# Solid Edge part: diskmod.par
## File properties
Author: Deepak Maini
Template: NORMENG.PAR
Last saved by: CADCIM
Revision: 6
Application: Solid Edge
Accuracy: 0.99
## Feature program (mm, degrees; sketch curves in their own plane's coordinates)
sketch for "unnamed Protrusion 1" plane through (0, 0, 0) normal (0, 0, 1) x-axis (1, 0, 0)
  line (-25.2008, 3.175) -> (-20.6375, 3.175)
  arc centre (-20.6375, 0) radius 3.175 from (-20.6375, 3.175) to (-20.6375, -3.175) cw
  line (-25.2008, -3.175) -> (-20.6375, -3.175)
  arc centre (0, 0) radius 25.4 from (-3.175, -25.2008) to (-25.2008, -3.175) cw
  line (-3.175, -25.2008) -> (-3.175, -20.6375)
  arc centre (0, -20.6375) radius 3.175 from (-3.175, -20.6375) to (3.175, -20.6375) cw
  line (3.175, -25.2008) -> (3.175, -20.6375)
  arc centre (0, 0) radius 25.4 from (25.2008, -3.175) to (3.175, -25.2008) cw
  line (25.2008, -3.175) -> (20.6375, -3.175)
  arc centre (20.6375, 0) radius 3.175 from (20.6375, -3.175) to (20.6375, 3.175) cw
  line (25.2008, 3.175) -> (20.6375, 3.175)
  arc centre (0, 0) radius 25.4 from (3.175, 25.2008) to (25.2008, 3.175) cw
  line (3.175, 25.2008) -> (3.175, 20.6375)
  arc centre (0, 20.6375) radius 3.175 from (3.175, 20.6375) to (-3.175, 20.6375) cw
  line (-3.175, 25.2008) -> (-3.175, 20.6375)
  arc centre (0, 0) radius 25.4 from (-25.2008, 3.175) to (-3.175, 25.2008) cw
extrude "unnamed Protrusion 1" add finite 3.175 along +normal
sketch for "Hole_1" plane through (0, 0, 3.175) normal (0, 0, 1) x-axis (1, 0, 0)
  hole centre (0, 0) bore radius 12.7
hole "Hole_1" diameter 25.4 through
sketch for "ExtrudedProtrusion_2" plane through (0, 0, 3.175) normal (0, 0, 1) x-axis (1, 0, 0)
extrude "ExtrudedProtrusion_2" add finite 15.875 along +normal
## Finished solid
Body 1: solid body, 25 faces, 62 edges, 40 vertices.
  Faces by surface: plane 16, cylinder 9
  Edges by curve: line 44, circle 18
Bounding box of the edges (mm): 50.402 x 50.402 x 19.050, from (-25.2008, -25.2008, 0) to (25.2008, 25.2008, 19.05).
Cylindrical faces by radius (mm): R3.175 x4, R12.7 x1, R25.4 x4
Planar faces by outward normal: +x 3, +y 3, +z 2, -x 3, -y 3, -z 2
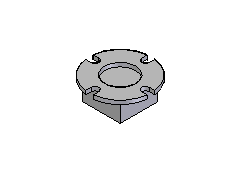
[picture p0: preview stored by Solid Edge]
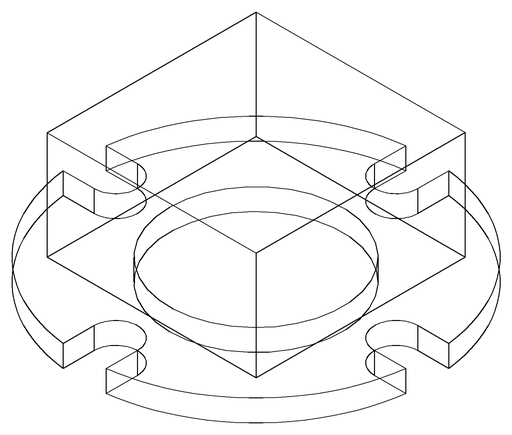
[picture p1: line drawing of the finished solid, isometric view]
